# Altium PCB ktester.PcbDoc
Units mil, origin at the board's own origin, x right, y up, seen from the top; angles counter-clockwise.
Board outline 2905 x 1065 mil, 2 copper layers (Top Layer, Bottom Layer); 20 components, 20 nets, 83 pads, 6 vias.
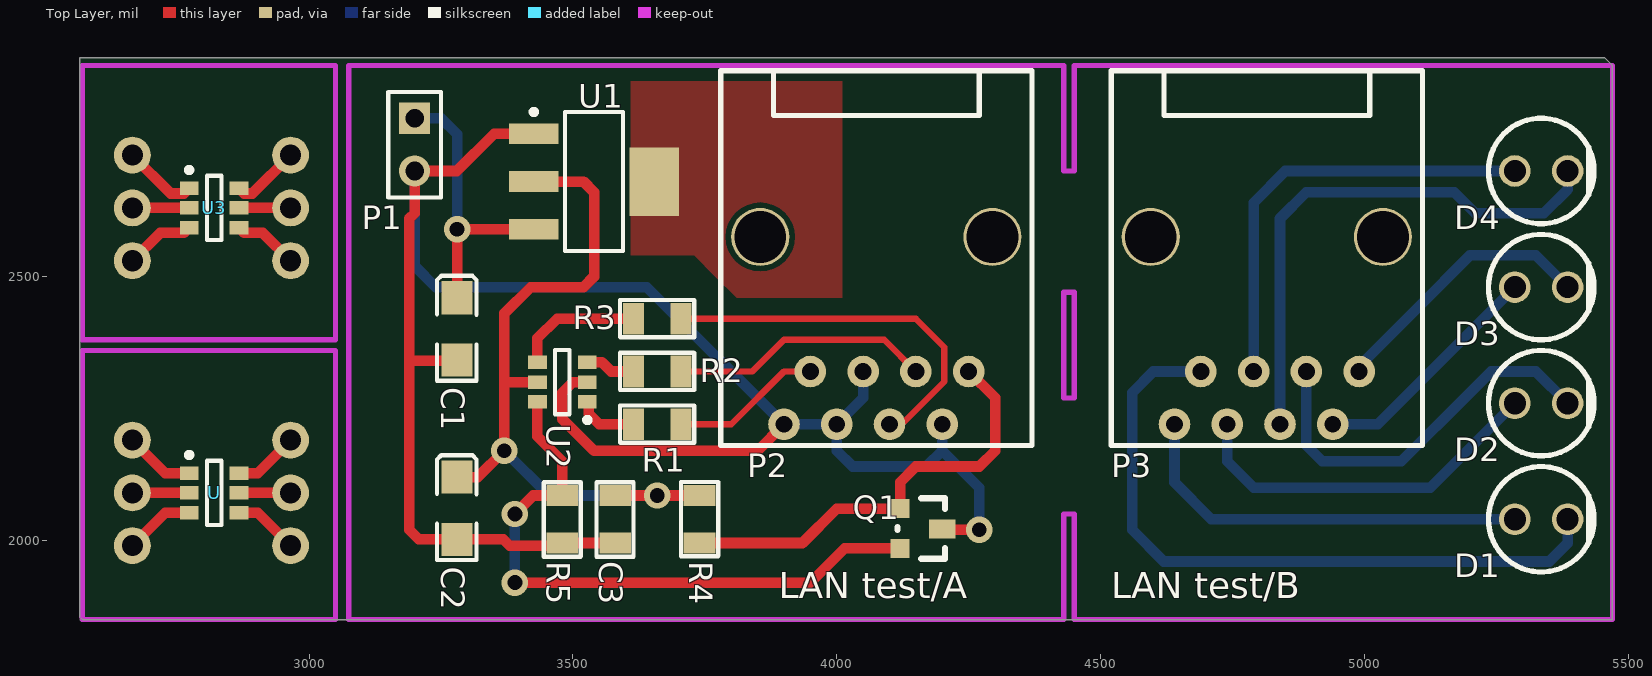
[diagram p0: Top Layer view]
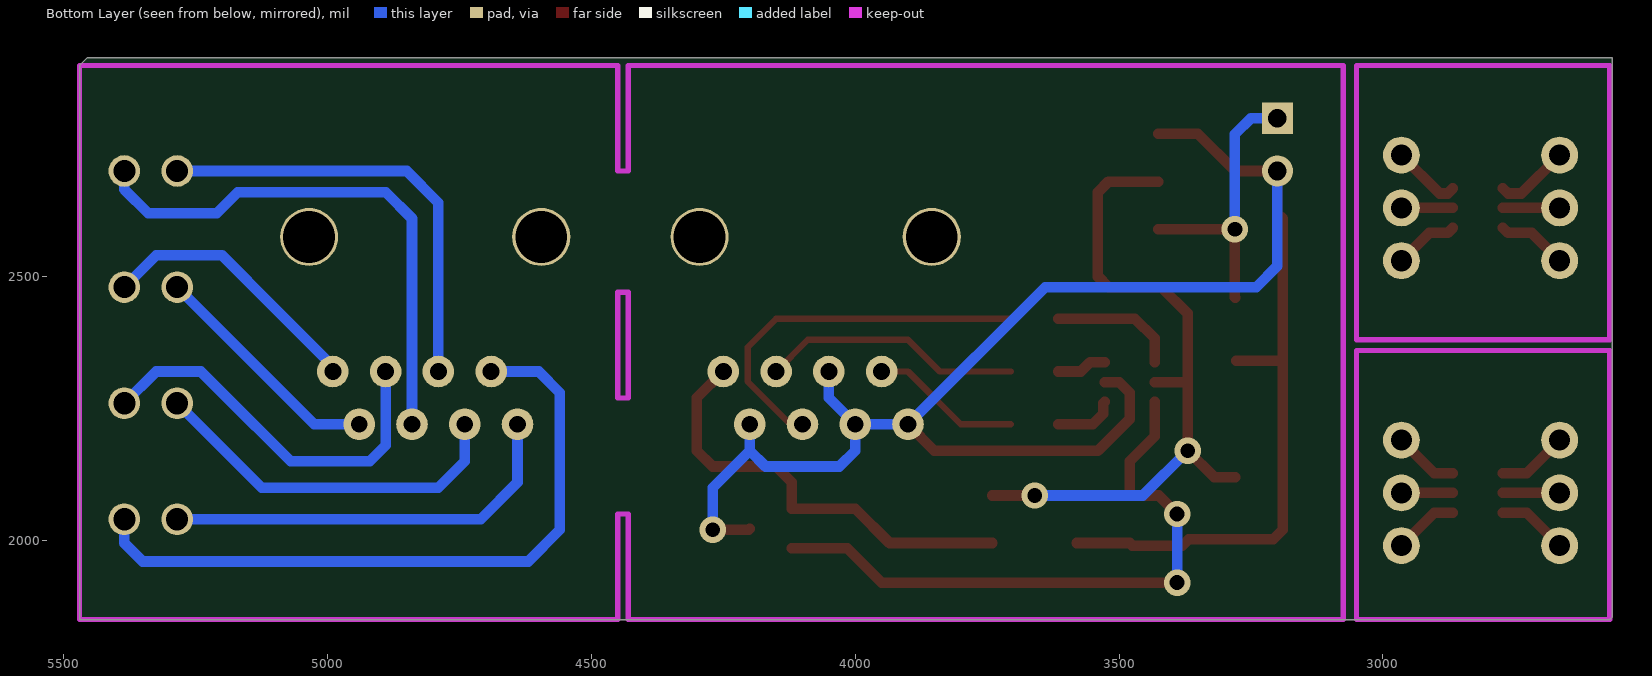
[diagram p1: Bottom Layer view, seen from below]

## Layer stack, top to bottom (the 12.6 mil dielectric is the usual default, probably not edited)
Top Layer: signal copper 1.4
Dielectric: dielectric 12.6, FR-4, Dk 4.8
Bottom Layer: signal copper 1.4

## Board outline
5470,2900 5455,2915 2565,2915 2565,1855 2570,1850 5470,1850

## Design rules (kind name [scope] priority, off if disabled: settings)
Clearance [All] p1: gap=10
PlaneConnect [All] p1: planeconnectstyle=Direct reliefexpansion=20 reliefentries=4 reliefconductorwidth=10 reliefairgap=10
PolygonConnect [All] p1: connectstyle=Direct reliefconductorwidth=10 reliefentries=4 polygonreliefangle="90 Angle"
RoutingVias [All] p1: holewidth=28 width=50 viastyle="Through Hole" minholewidth=28 minwidth=50 maxholewidth=28 maxwidth=50
SilkscreenOverComponentPads [All] p1: minsilkscreentomaskgap=10
SolderMaskExpansion [All] p1: expansion=4
Width [All] p1: maxlimit=50 minlimit=10 preferedwidth=20 bottomlayer_prefwidth=10
26 further rules are at their usual default settings.

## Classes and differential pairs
component class ktester: C1 C2 C3 D1 D2 D3 D4 P1 P2 P3 Q1 R1 R2 R3 R4 R5 U1 U2

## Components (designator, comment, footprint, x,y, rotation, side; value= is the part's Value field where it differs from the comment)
C1 "10uF" 3216(A) 3280,2460 r90 top
C2 "100uF" 3216(A) 3280,2120 r90 top
C3 "Cap" 0805 3580,2040 r90 top
D1 "LED" "LED 100MILS" 5385,2040 r180 top
D2 "LED" "LED 100MILS" 5385,2260 r180 top
D3 "LED" "LED 100MILS" 5385,2480 r180 top
D4 "LED" "LED 100MILS" 5385,2700 r180 top
P1 "Header 2H" HDR1X2 3200,2800 r270 top
P2 "MHDR1X8" RJ45/1 3780,2180 r0 top
P3 "MHDR1X8" RJ45/1 4520,2180 r0 top
Q1 "BS138" SOT-23 4120,2060 r270 top
R1 "Res2" 0805 3660,2220 r0 top
R2 "Res2" 0805 3660,2320 r0 top
R3 "Res2" 0805 3660,2420 r0 top
R4 "Res2" 0805 3740,2040 r270 top
R5 "Res2" 0805 3480,2040 r90 top
U "PIC10F200-E/OT" SOT-23-OT6_L 2820,2090 r0 top (schematic designator U2)
U1 "LM1117MP-5.0" MP04A_N 3540,2680 r0 top
U2 "PIC10F200-E/OT" SOT-23-OT6_L 3480,2300 r180 top
U3 "PIC10F200-E/OT" SOT-23-OT6_L 2820,2630 r0 top (schematic designator U2)

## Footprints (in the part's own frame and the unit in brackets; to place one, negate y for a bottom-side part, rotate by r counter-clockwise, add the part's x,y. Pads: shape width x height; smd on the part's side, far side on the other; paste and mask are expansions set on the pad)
0805 [mil]
  rect 40x60 smd: 1(-45,0) 2(45,0)
  silkscreen extent -71,-35 70,35
3216(A) [mm]
  rect 1.6x1.5 smd: 1(0,0) 2(-3,0)
  silkscreen extent -4,-0.95 1.05,0.95
HDR1X2 [mm] "Connector; Header; 2 Position"
  rect 1.5x1.5 hole 0.9: 1(0,0)
  round 1.5 hole 0.9: 2(2.54,0)
  silkscreen extent -1.27,-1.27 3.81,1.27
"LED 100MILS" [mil]
  round 60 hole 42: 1(0,0) 2(100,0)
  silkscreen extent -50,-100 150,100
MP04A_N [mm] "SOT223, 4-Leads, Body 6.5x3.5mm, Pitch 2.3mm, Lead Span 7mm, IPC Medium Density"
  rect 2.4x1 smd: 1(-2.9,2.3) 2(-2.9,0) 3(-2.9,-2.3)
  rect 2.4x3.3 smd: 4(2.9,0)
  silkscreen extent -3.02,-3.35 1.4,3.47, body extent -1.85,-3.35 1.85,3.35, height 1.8
RJ45/1 [mil] "RJ-45"
  round 60 hole 32: 1(120,40) 2(170,140) 3(220,40) 4(270,140) 5(320,40) 6(370,140) 7(420,40) 8(470,140)
  round 110 hole 98: 9(75,395) 10(515,395)
  silkscreen extent 0,0 590,710
SOT-23 [mil]
  rect 36x36 smd: 1(0,0) 2(75,0)
  rect 36x50 smd: 3(38,80)
  silkscreen extent -20,-5 95,85
SOT-23-OT6_L [mm] "SOT23, 6-Leads, Body 2.9x1.6mm, Pitch 0.95mm, Lead Span 2.7mm, IPC High Density"
  rect 0.9x0.65 smd: 1(-1.2,0.95) 2(-1.2,0) 3(-1.2,-0.95) 4(1.2,-0.95) 5(1.2,0) 6(1.2,0.95)
  silkscreen extent -1.32,-1.55 0.35,1.95, body extent -0.9,-1.55 0.9,1.55, height 1.45

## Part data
C1 C2: library part CP, "Capacitor"
C3: "Capacitor"
D1 D2 D3 D4: library part LED3, "Typical BLUE SiC LED"
P1: "Header, 2-Pin, Right Angle"
P2 P3: "Header, 8-Pin"
Q1: library part MOSFET-N, "N-Channel MOSFET"
R1 R2 R3 R4 R5: "Resistor"
U U2 U3: "8-bit Flash Microcontroller, 256 (x12-Bit words) Program Memory, 16 Bytes Data Memory, 6-Pin SOT-23, Extended Temperature"
U1: "800mA Low-Dropout Linear Regulator"

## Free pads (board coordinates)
  round 70 hole 40: 0(2665,2190) 0(2665,2730) 1(2665,2090) 1(2665,2630) 2(2665,1990) 2(2665,2530) 3(2965,1990) 3(2965,2530) 4(2965,2090) 4(2965,2630) 5(2965,2190) 5(2965,2730)

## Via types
v1: diameter 50, hole 28, Top Layer to Bottom Layer, 6 vias

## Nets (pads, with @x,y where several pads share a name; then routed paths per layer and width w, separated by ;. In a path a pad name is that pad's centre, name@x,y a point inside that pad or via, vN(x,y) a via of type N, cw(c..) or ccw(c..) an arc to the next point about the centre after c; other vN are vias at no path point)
GND: C1.2 C2.2 C3.1 P1.2 P2.1 P2.3 P2.4 P2.7 Q1.3 R5.1 U1.1 U2.2 | length 3802.5
  Top Layer w20: C1.2@3278.11,2340 3190,2340 ; U1.1 3350.55,2770.55 3280,2700 P1.2 3200,2620 3190,2610 3190,2340 ; U2.2 3500,2300 3480,2280 3480,2230 3540,2170 3850,2170 P2.1 ; C3.1 R5.1 3475,1990 3380,1990 3368.11,2001.89 C2.2 3208.11,2001.89 3190,2020 3190,2340 ; Q1.3 4202,2020 v1(4270,2020)
  Bottom Layer w20: P1.2 3200,2520 3240,2480 3640,2480 P2.1 P2.3 ; P2.4 4050,2270 P2.3 ; P2.7 4200,2170 ; v1(4270,2020) 4270,2100 4200,2170 ; P2.3 4000,2170 4030,2140 4170,2140 4200,2170
NetC1_1: C1.1 P1.1 U1.3 | length 548.2
  Top Layer w20: C1.1 3280.55,2460.55 v1(3280.55,2589.45) U1.3
  Bottom Layer w20: P1.1 3250,2800 3280.55,2769.45 v1(3280.55,2589.45)
NetD1_1: D1.1 P3.2 | length 1315.9
  Bottom Layer w20: P3.2 4600,2320 4560,2280 4560,2020 4620,1960 5350,1960 5385,1995 D1.1
NetD1_2: D1.2 P3.1 | length 784
  Bottom Layer w20: P3.1 4640,2110 4710,2040 D1.2
NetD2_1: D2.1 P3.6 | length 742.7
  Bottom Layer w20: P3.6 4890,2180 4920,2150 5070,2150 5200,2280 5240,2320 5325,2320 D2.1
NetD2_2: D2.2 P3.3 | length 702
  Bottom Layer w20: P3.3 4740,2150 4790,2100 5125,2100 5230,2205 D2.2
NetD3_1: D3.1 P3.8 | length 516.8
  Bottom Layer w20: P3.8 4990,2330 5100,2440 5200,2540 5325,2540 D3.1
NetD3_2: D3.2 P3.7 | length 452.7
  Bottom Layer w20: P3.7 5025,2220 5140,2335 D3.2
NetD4_1: D4.1 P3.5 | length 1025.9
  Bottom Layer w20: P3.5 4840,2610 4890,2660 5170,2660 5210,2620 5340,2620 5385,2665 D4.1
NetD4_2: D4.2 P3.4 | length 839.9
  Bottom Layer w20: P3.4 4790,2640 4850,2700 D4.2
NetP2_2: P2.2 R1.2 | length 286.4
  Top Layer w12: R1.2 3800,2220 3900,2320 P2.2
NetP2_5: P2.5 R3.2 | length 724
  Top Layer w12: R3.2 4150,2420 4204,2366 4204,2300.95 4123.05,2220 P2.5
NetP2_6: P2.6 R2.2 | length 494.7
  Top Layer w12: R2.2 3840,2320 3900,2380 4090,2380 P2.6
NetP2_8: P2.8 Q1.1 R4.2 | length 832.5
  Top Layer w20: R4.2 3935,1995 4000,2060 Q1.1 4120,2110 4150,2140 4270,2140 4300,2170 4300,2270 P2.8
NetQ1_2: Q1.2 R5.2 U2.6 | length 1188.6
  Top Layer w20: v1(3390,1920) 3950,1920 4015,1985 Q1.2 ; v1(3390,2050) 3425,2085 R5.2 3480,2150 3432.76,2197.24 U2.6
  Bottom Layer w20: v1(3390,1920) v1(3390,2050)
NetR1_1: R1.1 U2.1 | length 117
  Top Layer w20: U2.1 3530,2259.84 3530,2240 3550,2220 R1.1
NetR2_1: R2.1 U2.3 | length 95
  Top Layer w20: U2.3 3555.02,2337.4 3572.43,2320 R2.1
NetR3_1: R3.1 U2.4 | length 243
  Top Layer w20: U2.4 3432.76,2382.76 3470,2420 R3.1
NewNet_01: U1.4
VCC: C2.1 C3.2 R4.1 U1.2 U2.5 | length 1400.1
  Top Layer w20: C2.1 3320,2120 v1(3370,2170) 3370,2300 ; U1.2 3520,2680 3540,2660 3540,2500 3520,2480 3420,2480 3370,2430 3370,2300 ; U2.5 3370,2300 ; C3.2 v1(3660,2085) R4.1
  Bottom Layer w20: v1(3370,2170) 3455,2085 v1(3660,2085)
pads on no net: P2.9 P2.10 P3.9 P3.10 U3.1 U3.2 U3.3 U3.4 U3.5 U3.6 U.1 U.2 U.3 U.4 U.5 U.6
copper on no net: | length 1457.1
  Top Layer w20: 2665,1990 2727.6,2052.6 2772.76,2052.6 ; 2665,2090 2772.76,2090 ; 2665,2190 2727.6,2127.4 2772.76,2127.4 ; 2665,2530 2717.6,2582.6 2762.76,2582.6 2772.76,2592.6 ; 2665,2630 2772.76,2630 ; 2665,2730 2737.6,2657.4 2762.76,2657.4 2772.76,2667.4 ; 2867.24,2052.6 2902.4,2052.6 2965,1990 ; 2867.24,2090 2965,2090 ; 2867.24,2127.4 2902.4,2127.4 2965,2190 ; 2867.24,2592.6 2877.24,2582.6 2912.4,2582.6 2965,2530 ; 2867.24,2630 2965,2630 ; 2867.24,2667.4 2877.24,2657.4 2892.4,2657.4 2965,2730

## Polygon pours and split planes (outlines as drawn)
NewNet_01 on Top Layer "GND-top" (solid, pour order 1000): 3610,2730 3610,2870 4010,2870 4010,2490 4010,2460 3810,2460 3770,2500 3730,2540 3610,2540

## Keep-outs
Keep-Out Layer:
  lines w10: 2570,1850 3050,1850 3050,2360 2570,2360 2570,1850 ; 2570,2380 2570,2900 3050,2900 3050,2380 2570,2380 ; 3075,1850 3075,2900 4430,2900 4430,2700 4450,2700 4450,2900 5470,2900 5470,1850 4450,1850 4450,2050 4430,2050 4430,1850 3075,1850 ; 4430,2270 4430,2470 4450,2470 4450,2270 4430,2270

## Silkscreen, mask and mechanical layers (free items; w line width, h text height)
Top Overlay:
  text "LAN test/A" at 3890,1890 h50
  text "LAN test/B" at 4520,1890 h50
